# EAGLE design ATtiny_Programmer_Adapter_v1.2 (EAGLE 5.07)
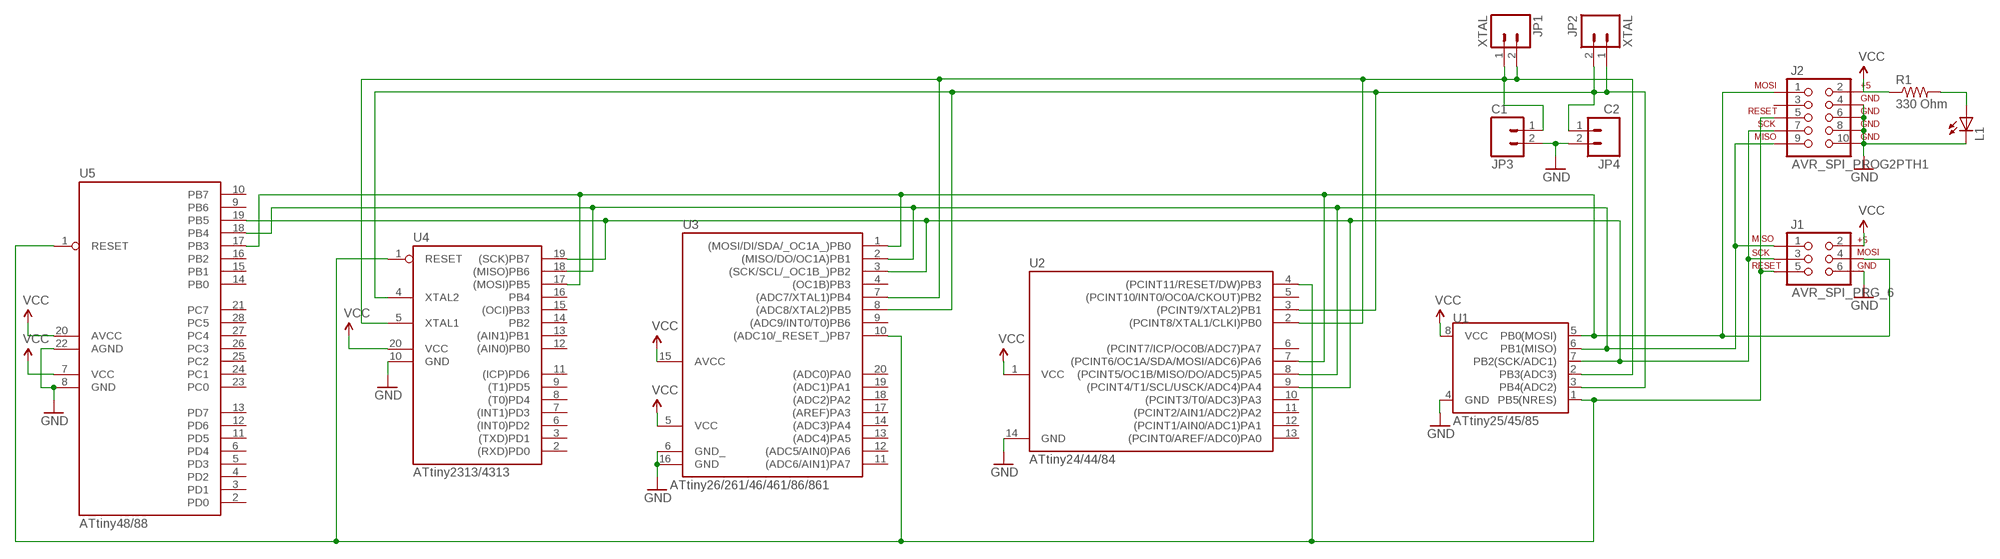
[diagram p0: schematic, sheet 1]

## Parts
J1  AVR_SPI_PRG_6  [2X3_2]
J2  AVR_SPI_PROG2PTH1  [AVR_ICSP_3]
JP1  XTAL  M02PTH  [1X02]
JP2  XTAL  M02PTH  [1X02]
JP3  C1  M02PTH  [1X02]
JP4  C2  M02PTH  [1X02]
L1  LEDCHIP-LED0805  [CHIP-LED0805]
R1  330 Ohm  R-US_R0805_2  [R0805_2]
U1  ATtiny25/45/85  ATTINY45DIP8  [DIP08]
U2  ATtiny24/44/84  TINY24/44/84  [DIP14]
U3  ATtiny26/261/46/461/86/861  TINY26  [DIP20]
U4  ATtiny2313/4313  AT90S2313  [DIP20]
U5  ATtiny48/88  TINY48-88DIP28  [DIP28]

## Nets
GND: J1.6 J2.4 J2.6 J2.8 J2.10 JP3.2 JP4.2 L1.C U1.4(GND) U2.14(GND) U3.6(GND_) U3.16(GND) U4.10(GND) U5.8(GND) U5.22(AGND)
MISO: J1.1 J2.9 U1.6(PB1(MISO)) U2.8((PCINT5/OC1B/MISO/DO/ADC5)PA5) U3.2((MISO/DO/OC1A)PB1) U4.18((MISO)PB6) U5.18(PB4)
MOSI: J1.4 J2.1 U1.5(PB0(MOSI)) U2.7((PCINT6/OC1A/SDA/MOSI/ADC6)PA6) U3.1((MOSI/DI/SDA/_OC1A_)PB0) U4.17((MOSI)PB5) U5.17(PB3)
N$1: JP1.1 JP1.2 JP3.1 U1.2(PB3(ADC3)) U2.2((PCINT8/XTAL1/CLKI)PB0) U3.7((ADC7/XTAL1)PB4) U4.5(XTAL1)
N$6: L1.A R1.2
N$10: JP2.1 JP2.2 JP4.1 U1.3(PB4(ADC2)) U2.3((PCINT9/XTAL2)PB1) U3.8((ADC8/XTAL2)PB5) U4.4(XTAL2)
RESET: J1.5 J2.5 U1.1(PB5(NRES)) U2.4((PCINT11/RESET/DW)PB3) U3.10((ADC10/_RESET_)PB7) U4.1(RESET) U5.1(RESET)
SCK: J1.3 J2.7 U1.7(PB2(SCK/ADC1)) U2.9((PCINT4/T1/SCL/USCK/ADC4)PA4) U3.3((SCK/SCL/_OC1B_)PB2) U4.19((SCK)PB7) U5.19(PB5)
VCC: J1.2 J2.2 R1.1 U1.8(VCC) U2.1(VCC) U3.5(VCC) U3.15(AVCC) U4.20(VCC) U5.7(VCC) U5.20(AVCC)
Unconnected: J2.3 U2.5((PCINT10/INT0/OC0A/CKOUT)PB2) U2.6((PCINT7/ICP/OC0B/ADC7)PA7) U2.10((PCINT3/T0/ADC3)PA3) U2.11((PCINT2/AIN1/ADC2)PA2) U2.12((PCINT1/AIN0/ADC1)PA1) U2.13((PCINT0/AREF/ADC0)PA0) U3.4((OC1B)PB3) U3.9((ADC9/INT0/T0)PB6) U3.11((ADC6/AIN1)PA7) U3.12((ADC5/AIN0)PA6) U3.13((ADC4)PA5) U3.14((ADC3)PA4) U3.17((AREF)PA3) U3.18((ADC2)PA2) U3.19((ADC1)PA1) U3.20((ADC0)PA0) U4.2((RXD)PD0) U4.3((TXD)PD1) U4.6((INT0)PD2) U4.7((INT1)PD3) U4.8((T0)PD4) U4.9((T1)PD5) U4.11((ICP)PD6) U4.12((AIN0)PB0) U4.13((AIN1)PB1) U4.14(PB2) U4.15((OCI)PB3) U4.16(PB4) U5.2(PD0) U5.3(PD1) U5.4(PD2) U5.5(PD3) U5.6(PD4) U5.9(PB6) U5.10(PB7) U5.11(PD5) U5.12(PD6) U5.13(PD7) U5.14(PB0) U5.15(PB1) U5.16(PB2) U5.21(PC7) U5.23(PC0) U5.24(PC1) U5.25(PC2) U5.26(PC3) U5.27(PC4) U5.28(PC5)

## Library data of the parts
J1 = SparkFun:AVR_SPI_PRG_6: AVR ISP 6 Pin This is the reduced ISP connector for AVR programming. Common on Arduino. This footprint will take up less PCB space and can be used with a 10-pin to 6-pin adapter such as SKU: BOB-08508
J2 = SparkFun:AVR_SPI_PROG2: AVR ICSP Header This is the standard AVR In Circuit Serial Programming header. Minimal, but includes pin one indicator. Works with standard Olimex programmers. Also look for the 6-pin reduced version. Spark Fun Electronics SKU: PRT-00778
JP1-JP4 = SparkFun:M02: Header 2
L1 = adafruit:LED: LED
R1 = adafruit:R-US_: RESISTOR, American symbol
U1 = SparkFun:ATTINY45: Atmel ATTiny45
U2 = avr-5:TINY24/44/84
U3 = avr-5:TINY26
U4 = avr-5:AT90S2313: MICROCONTROLLER 2 Kbytes FLASH 128 bytes SRAM 128 bytes EEPROM UART
U5 = atmel:TINY48-88

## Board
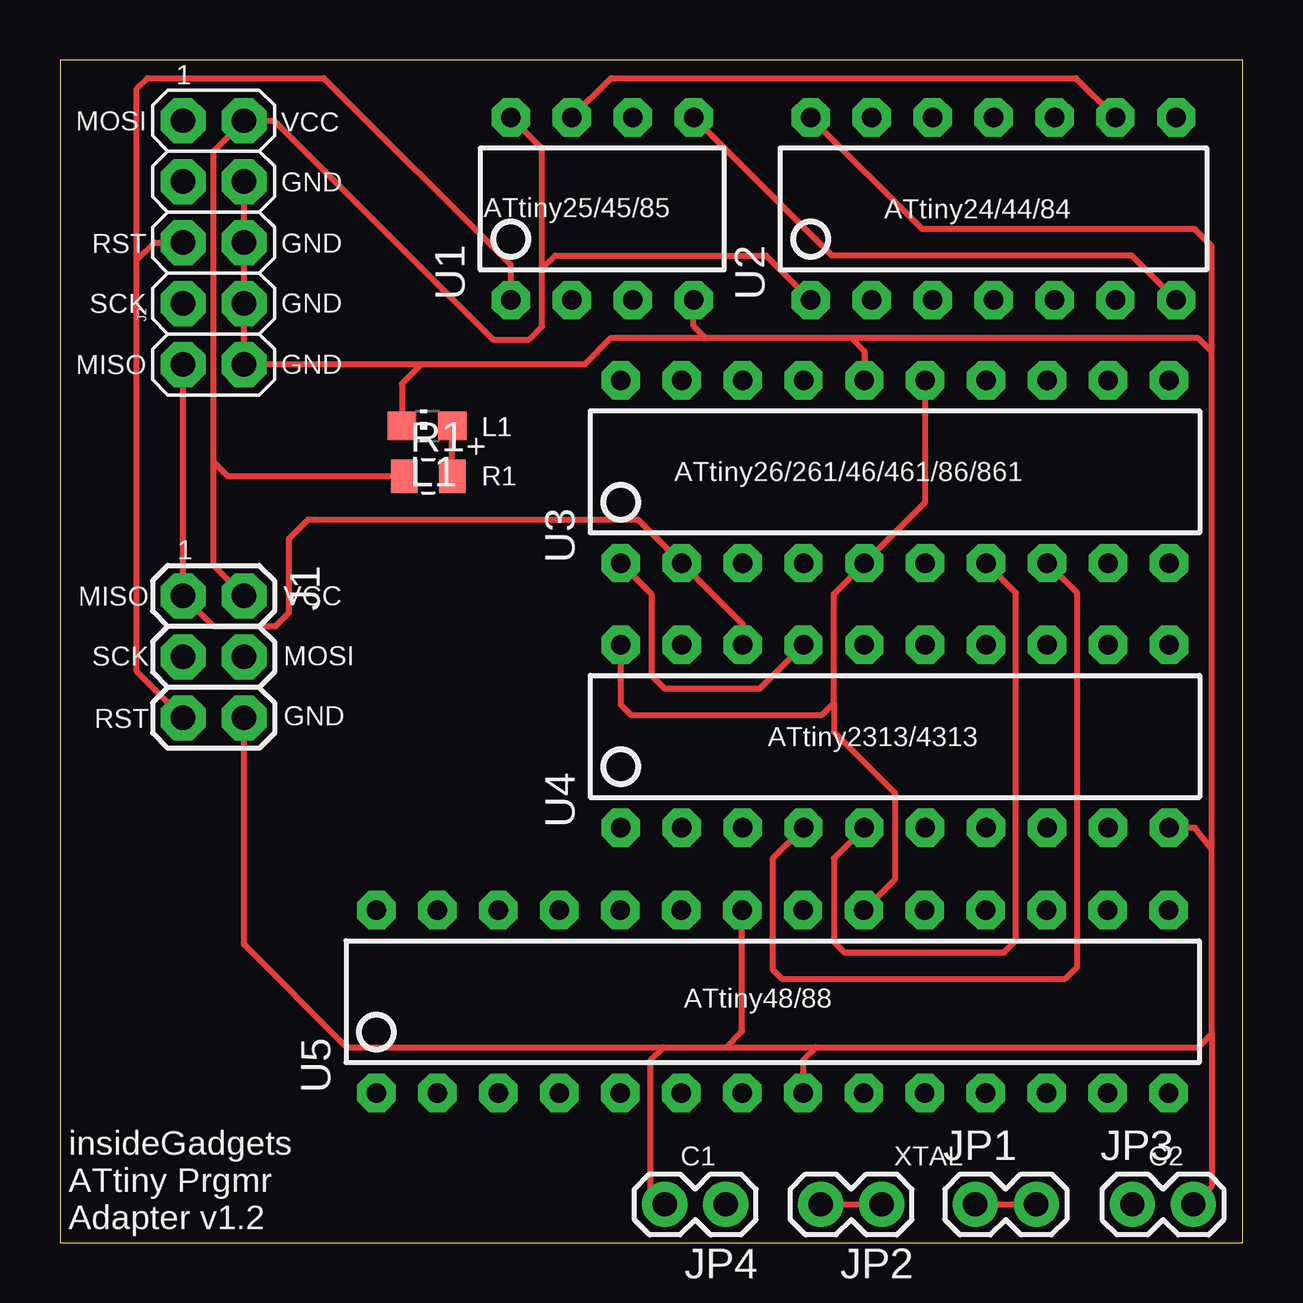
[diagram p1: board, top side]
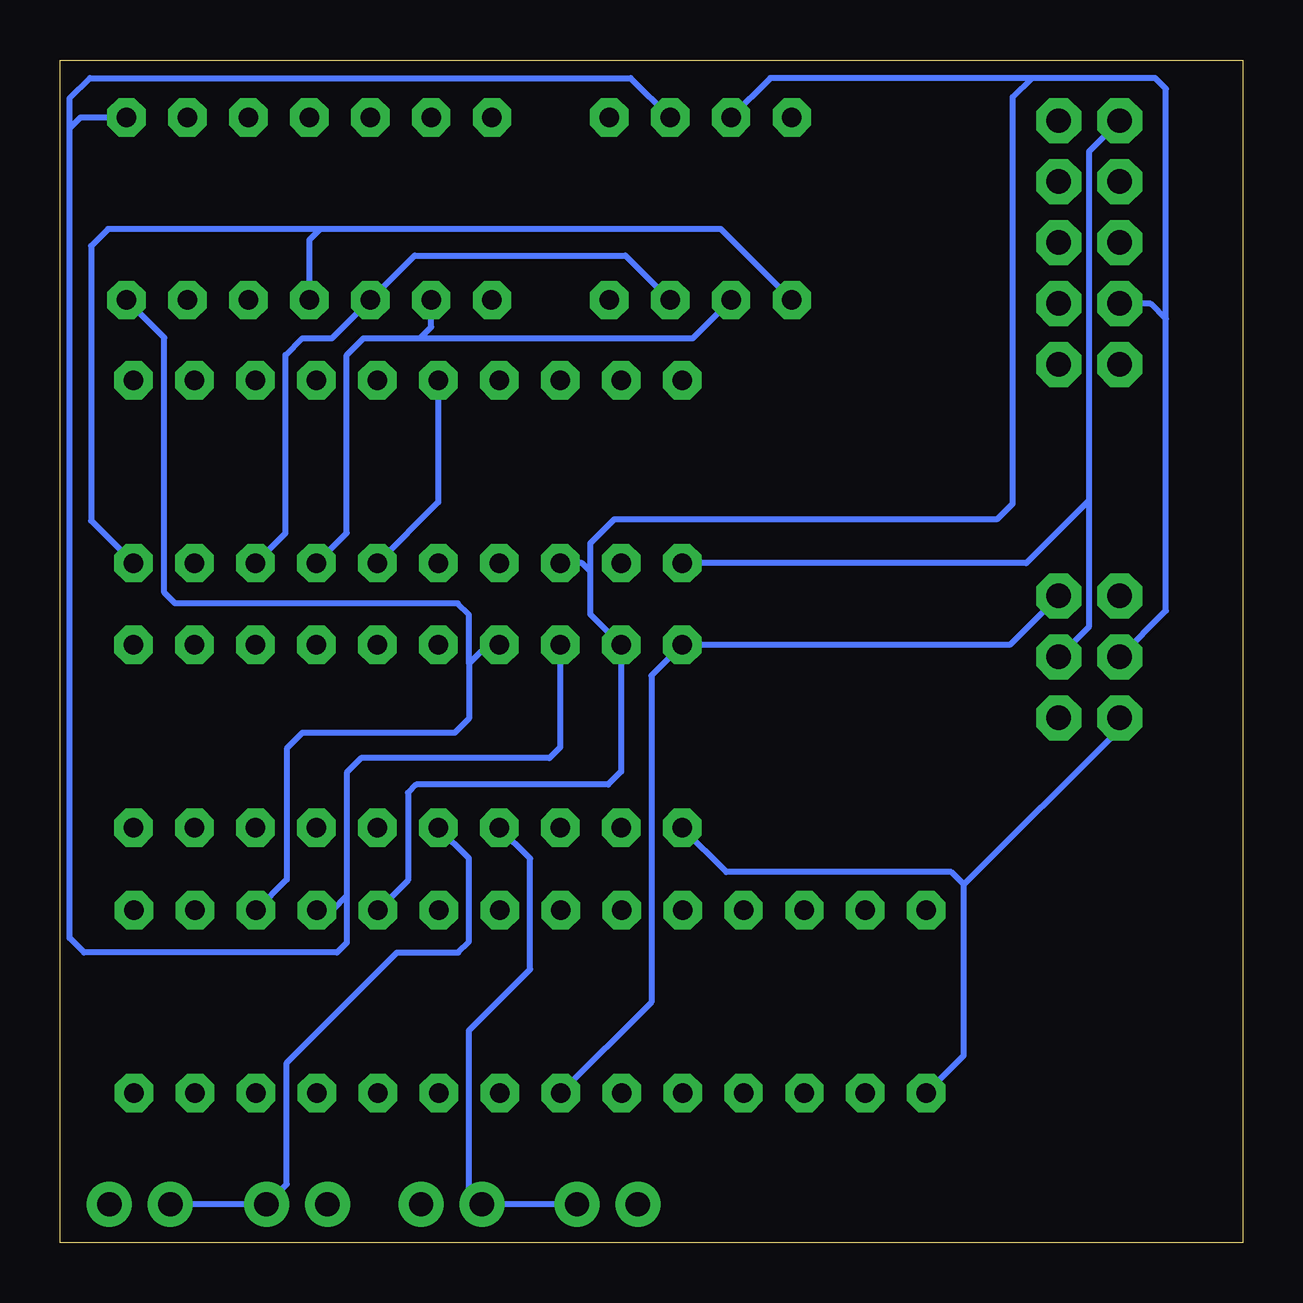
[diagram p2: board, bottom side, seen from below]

Size 49.3 x 49.3 mm. Coordinates in mm from the lower left corner, seen from the top.
Outline: 0,0 49.3,0 49.3,49.3 0,49.3 0,0
Copper layers (1*16): Top 0.035mm / dielectric 1.5mm / Bottom 0.035mm
Design rules "ITead_rule": minimum track width 6mil, minimum drill 12mil, track to track 6mil, track to pad 6mil, pad to pad 6mil, via to via 6mil, smd to smd 0mil, copper to edge 10mil, drill to drill 10mil, minimum pad ring 10mil, minimum via ring 6mil, stop-mask expansion 2mil, vias tented up to drill 100mil, thermal gap 10mil

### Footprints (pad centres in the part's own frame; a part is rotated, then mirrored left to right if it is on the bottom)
2X3_2 = drill 1.016 pad 1.88 octagon: 1 -2.54,-1.27; 2 -2.54,1.27; 3 0,-1.27; 4 0,1.27; 5 2.54,-1.27; 6 2.54,1.27
AVR_ICSP_3 = drill 1.016 pad 1.88 octagon: 1 -1.27,5.08; 2 1.27,5.08; 3 -1.27,2.54; 4 1.27,2.54; 5 -1.27,0; 6 1.27,0; 7 -1.27,-2.54; 8 1.27,-2.54; 9 -1.27,-5.08; 10 1.27,-5.08
1X02 = drill 1.016 pad 1.88 round: 1 0,0; 2 2.54,0
CHIP-LED0805 = smd 1.2 x 1.2: A 0,-1.05; C 0,1.05
R0805_2 = smd 1.1 x 1.4: 1 -1,0; 2 1,0
DIP08 = drill 0.813 pad 1.6 octagon: 1 -3.81,-3.81; 2 -1.27,-3.81; 3 1.27,-3.81; 4 3.81,-3.81; 5 3.81,3.81; 6 1.27,3.81; 7 -1.27,3.81; 8 -3.81,3.81
DIP14 = drill 0.813 pad 1.6 octagon: 1 -3.81,-3.81; 2 -1.27,-3.81; 3 1.27,-3.81; 4 3.81,-3.81; 5 6.35,-3.81; 6 8.89,-3.81; 7 11.43,-3.81; 8 11.43,3.81; 9 8.89,3.81; 10 6.35,3.81; 11 3.81,3.81; 12 1.27,3.81; 13 -1.27,3.81; 14 -3.81,3.81
DIP20 = drill 0.813 pad 1.6 octagon: 1 -11.43,-3.81; 2 -8.89,-3.81; 3 -6.35,-3.81; 4 -3.81,-3.81; 5 -1.27,-3.81; 6 1.27,-3.81; 7 3.81,-3.81; 8 6.35,-3.81; 9 8.89,-3.81; 10 11.43,-3.81; 11 11.43,3.81; 12 8.89,3.81; 13 6.35,3.81; 14 3.81,3.81; 15 1.27,3.81; 16 -1.27,3.81; 17 -3.81,3.81; 18 -6.35,3.81; 19 -8.89,3.81; 20 -11.43,3.81
DIP28 = drill 0.813 pad 1.6 octagon: 1 -16.51,-3.81; 2 -13.97,-3.81; 3 -11.43,-3.81; 4 -8.89,-3.81; 5 -6.35,-3.81; 6 -3.81,-3.81; 7 -1.27,-3.81; 8 1.27,-3.81; 9 3.81,-3.81; 10 6.35,-3.81; 11 8.89,-3.81; 12 11.43,-3.81; 13 13.97,-3.81; 14 16.51,-3.81; 15 16.51,3.81; 16 13.97,3.81; 17 11.43,3.81; 18 8.89,3.81; 19 6.35,3.81; 20 3.81,3.81; 21 1.27,3.81; 22 -1.27,3.81; 23 -3.81,3.81; 24 -6.35,3.81; 25 -8.89,3.81; 26 -11.43,3.81; 27 -13.97,3.81; 28 -16.51,3.81

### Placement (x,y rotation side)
J1  6.4,24.42 270 top
J2  6.4,41.69 0 top
JP1  38.15,1.6 0 top
JP2  34.25,1.6 180 top
JP3  44.7,1.6 0 top
JP4  27.75,1.6 180 top
L1  15.3,34.05 90 top
R1  15.35,31.95 0 top
U1  22.6,43.1 0 top
U2  35.1,43.1 0 top
U3  34.8,32.14 0 top
U4  34.8,21.11 0 top
U5  29.7,10.05 0 top

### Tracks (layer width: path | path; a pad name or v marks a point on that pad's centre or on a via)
GND
  Top 0.254: U5.8 30.97,7.62 31.5,8.15 | U2.14 35.94,42.25 47.3,42.25 48,41.55 48,37.15 | U4.10 47.31,17.3 48,16.39 | J2.4 J2.6 J2.8 J2.10 15.05,36.61 | 48,16.39 48,37.15 | 33,37.7 47.45,37.7 48,37.15 | U1.4 26.41,38.21 26.88,37.73 | U3.16 33.53,37.17 33,37.7 | 25.15,8.15 27.75,8.15 | 27.75,8.15 31.5,8.15 | JP4.2 24.6,2.21 24.6,7.6 25.15,8.15 | 48,8.7 48,16.39 | 31.5,8.15 47.45,8.15 48,8.7 | JP3.2 48,2.36 48,8.7 | U5.22 28.43,8.83 27.75,8.15 | 33,37.7 26.92,37.7 26.88,37.73 | 26.88,37.73 26.85,37.7 22.95,37.7 21.86,36.61 16.1,36.61 15.05,36.61 | 25.15,8.15 11.95,8.15 7.67,12.43 J1.6 | L1.C 14.25,35.81 15.05,36.61
  Bottom 0.254: U3.6 33.53,30.87 U3.16
MISO
  Top 0.254: U4.18 28.45,25.79 U3.2 24.09,30.15 10.35,30.15 9.55,29.35 9.55,26.26 8.99,25.7 6.39,25.7 J1.1 J2.9
  Bottom 0.254: U1.6 25.51,48.55 48.05,48.55 48.9,47.7 48.9,46.45 | 48.9,46.45 48.9,12.7 48.3,12.1 37.75,12.1 37.35,12.5 37.35,14.45 | U4.18 28.45,20.65 28.9,20.2 36.75,20.2 37.35,19.6 37.35,14.45 | U5.18 37.94,13.86 37.35,14.45 | U2.8 48.44,46.91 48.9,46.45
MOSI
  Top 0.254: U4.17 29.17,23.1 25.2,23.1 24.65,23.65 24.65,27.05 U3.1 | U1.5 32.17,41.15 44.67,41.15 U2.7
  Bottom 0.254: U2.7 44.95,37.72 44.95,27.1 44.5,26.65 32.72,26.65 32.25,26.18 32.25,24.15 | U4.17 31.48,24.92 32.25,24.15 | 32.25,24.15 32.25,21.85 32.85,21.25 39.2,21.25 39.85,20.6 39.85,15.14 U5.17 | J1.4 6.4,25.69 6.4,30.95 | 6.4,30.95 6.4,45.49 J2.1 | U3.1 9.02,28.33 6.4,30.95
N$1
  Top 0.254: U4.5 32.25,16.02 32.25,12.55 32.7,12.1 39.35,12.1 39.85,12.6 39.85,27.09 U3.7 | JP1.1 JP1.2
  Bottom 0.254: U1.2 22.92,37.7 34.3,37.7 | 34.3,37.7 36.65,37.7 37.35,37 37.35,29.59 U3.7 | U2.2 33.83,38.17 34.3,37.7 | U4.5 32.25,16.02 32.25,12.55 32.7,12.1 35.25,12.1 39.85,7.5 39.85,2.44 JP1.2 JP3.1
N$6
  Top 0.254: R1.2 L1.A
N$10
  Top 0.254: U3.8 42.4,27.08 42.4,11.5 41.9,11 30.1,11 29.7,11.4 29.7,16.01 U4.4 | JP2.2 JP2.1
  Bottom 0.254: U3.8 39.9,29.58 39.9,37 39.2,37.7 37.96,37.7 U2.3 34.51,41.15 25.73,41.15 U1.3 | U4.4 29.7,16.01 29.7,11.4 32.25,8.85 32.25,2.14 JP2.2 JP4.1
RESET
  Top 0.254: J1.5 3.2,23.81 3.2,40.95 | 3.2,40.95 3.2,48.1 3.65,48.55 11,48.55 18.79,40.76 U1.1 | J2.5 3.94,41.69 3.2,40.95
  Bottom 0.254: U1.1 21.75,42.25 38.45,42.25 | 38.45,42.25 47.3,42.25 48,41.55 48,30.1 U3.10 | U2.4 38.91,41.79 38.45,42.25 | U4.1 21.52,15.45 12.15,15.45 11.63,14.93 | U5.1 11.63,7.8 11.63,14.93 | 11.63,14.93 5.13,21.42 J1.5
SCK
  Top 0.254: U1.7 22.97,48.55 42.35,48.55 U2.9
  Bottom 0.254: U5.19 34.8,15.11 34.8,18.75 34.45,19.1 26.45,19.1 25.91,19.64 U4.19 27.2,26.2 27.2,28 | J1.3 3.2,26.35 3.2,38.5 | J2.7 3.84,39.14 3.2,38.5 | U3.3 27.53,28.33 27.2,28 | 27.2,28 27.2,29.15 26.2,30.15 10.25,30.15 9.6,30.8 9.6,47.75 8.8,48.55 | 3.2,38.5 3.2,48.1 3.65,48.55 8.8,48.55 | 8.8,48.55 19.69,48.55 U1.7
VCC
  Top 0.254: U2.1 29.43,41.15 20.65,41.15 20.1,40.6 | 6.4,32.55 6.4,28.23 J1.2 | 6.4,32.55 6.4,45.49 J2.2 8.93,46.77 18.05,37.65 19.55,37.65 20.1,38.2 20.1,40.6 | U4.20 23.37,22.43 23.8,22 31.75,22 32.25,22.5 | 32.25,22.5 32.25,27.05 U3.5 36.07,30.87 U3.15 | U5.20 34.8,15.15 34.8,18.75 32.25,21.3 32.25,22.5 | U1.8 20.1,45.6 20.1,40.6 | R1.1 7,31.95 6.4,32.55
  Bottom 0.254: U4.20 | U5.7 24.65,10.02 24.65,23.64 U4.20 | J1.2 9.71,24.92 U4.20

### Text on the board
tPlace: 1 | MOSI | VCC | GND | ATtiny25/45/85 | ATtiny24/44/84 | RST | GND | SCK | GND | MISO | GND | L1 | R1 | ATtiny26/261/46/461/86/861 | 1 | MISO | VCC | SCK | MOSI | RST | GND | ATtiny2313/4313 | ATtiny48/88 | insideGadgets | C1 | XTAL | C2 | ATtiny Prgmr | Adapter v1.2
